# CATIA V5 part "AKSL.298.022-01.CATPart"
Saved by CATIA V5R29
Part number: АКСЛ.298.022-01
Material "Steel": density 7860 kg/m3, Young's modulus 2e+11 Pa, Poisson ratio 0.266, thermal expansion 1.17e-05 1/K
Bounding box of the stored display mesh (mm): x -149 to 149, y -51 to 52, z -52 to 51
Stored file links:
  Z:\ООО Аксель\Соединения бруса\Соединения бруса\Соединения из листа\АКСЛ.298.020 (Дуо)\AKSL.298.022-01.CATPart
  Z:\ООО Аксель\Соединения бруса\Соединения бруса\Соединения из листа\АКСЛ.298.020 (Дуо)\AKSL.298.022.CATPart
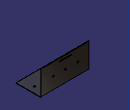
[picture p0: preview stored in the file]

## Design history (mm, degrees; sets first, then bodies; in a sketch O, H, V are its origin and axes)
Set1 "External References"
  DatumSurface1 "Extrude.1": linked copy from another document
  DatumCurve1 "2 угол Profile.2": linked copy from another document
  Plane1 "OutputPlane.1 (Line.4)": linked copy from another document
Body1 (main body)
  Body2 "Body from original PartBody"
    Solid1: linked copy from another document
  Assemble1: tool Body2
